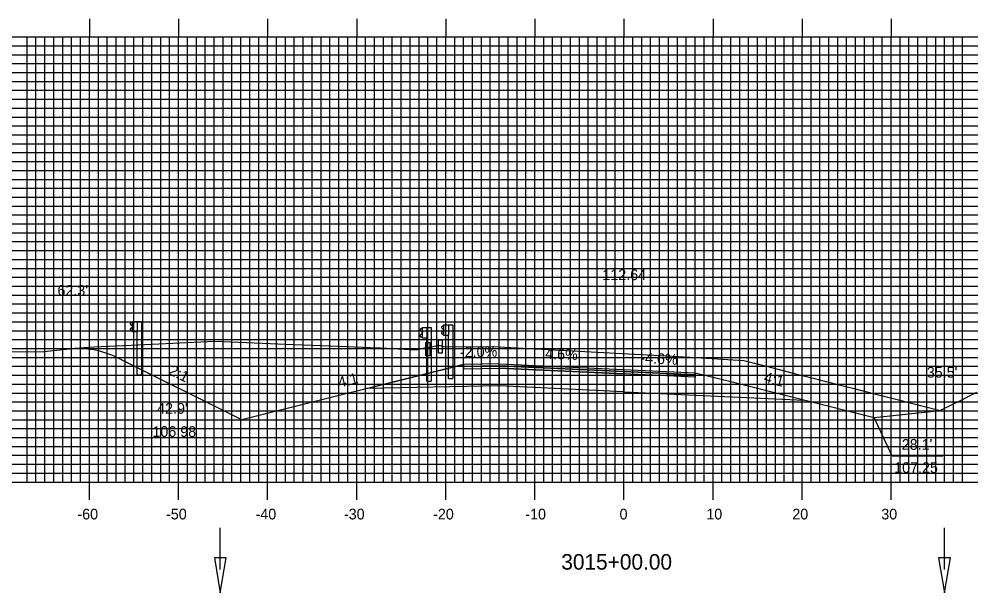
# Model space of a CAD drawing. Extents: x 1684799 to 1685142, y 461260 to 461480.
# Drawn here: x 1684896.8 to 1685003.7, y 461325.6 to 461390.1 of the extents above; entities that cross this region are included whole.
import ezdxf

# ---------------------------------------------------------------- set-up
doc = ezdxf.new("R2010")
doc.units = 0
for name, color, linetype in [('ANNOTATION', 7, 'Continuous'), ('D_Drainage_Ditch_Line', 7, 'Continuous'), ('D_Roadway_Centerline_Text', 7, 'Continuous'), ('D_Roadway_Edge_Shoulder', 7, 'Continuous'), ('D_Roadway_Edge_TW', 7, 'Continuous'), ('D_Roadway_Pavement', 7, 'Continuous'), ('D_Roadway_SlopeLines', 7, 'Continuous'), ('D_Roadway_SubGrade', 7, 'Continuous'), ('D_Text_Standard', 7, 'Continuous'), ('H_V ANNOTATION', 7, 'Continuous'), ('MAJOR', 7, 'Continuous'), ('MINOR', 7, 'Continuous'), ('PDRAIN', 7, 'Continuous'), ('S_Curb_Type_1', 7, 'Continuous'), ('S_Guardrail_Beam', 7, 'Continuous'), ('S_Roadway_Centerline', 7, 'Continuous')]:
    doc.layers.add(name, color=color, linetype=linetype)

msp = doc.modelspace()

# ---------------------------------------------------------------- linework, layer by layer
at = {"layer": 'ANNOTATION'}
msp.add_line((1684978.18, 461351.71), (1684978.94, 461351.52), dxfattribs=at)
msp.add_lwpolyline([(1685000.53, 461340.97), (1684994.84, 461340.97), (1684992.82, 461345.32)], dxfattribs=at)
at = {"layer": 'D_Drainage_Ditch_Line'}
for p, q in [((1684919.41, 461328.23), (1684919.41, 461332.93)), ((1685000.71, 461328.23), (1685000.71, 461332.93))]:
    msp.add_line(p, q, dxfattribs=at)
for points in [[(1684920.06, 461329.55), (1684918.75, 461329.55), (1684919.41, 461325.61)], [(1685001.37, 461329.55), (1685000.05, 461329.55), (1685000.71, 461325.61)]]:
    msp.add_lwpolyline(points, close=True, dxfattribs=at)
at = {"layer": 'D_Roadway_Edge_Shoulder'}
for points in [[(1684950.72, 461351.36), (1684946.72, 461351.28), (1684946.72, 461351.03), (1684950.72, 461351.11)], [(1684950.72, 461351.11), (1684946.72, 461351.03), (1684946.72, 461350.78), (1684950.72, 461350.86)], [(1684964.72, 461350.72), (1684972.72, 461350.35), (1684972.72, 461350.1), (1684964.72, 461350.47)], [(1684964.72, 461350.47), (1684972.72, 461350.1), (1684972.72, 461349.85), (1684964.72, 461350.22)]]:
    msp.add_lwpolyline(points, close=True, dxfattribs=at)
at = {"layer": 'D_Roadway_Edge_TW'}
msp.add_lwpolyline([(1684950.72, 461351.36), (1684964.72, 461350.72), (1684964.72, 461350.47), (1684950.72, 461351.11)], close=True, dxfattribs=at)
at = {"layer": 'D_Roadway_Pavement'}
msp.add_lwpolyline([(1684950.72, 461351.11), (1684964.72, 461350.47), (1684964.72, 461350.22), (1684950.72, 461350.86)], close=True, dxfattribs=at)
for points in [[(1684950.72, 461351.11), (1684950.72, 461350.86)], [(1684950.72, 461351.11), (1684950.72, 461350.86)], [(1684964.72, 461350.47), (1684964.72, 461350.22)], [(1684964.72, 461350.47), (1684964.72, 461350.22)], [(1684964.72, 461350.47), (1684964.72, 461350.22)]]:
    msp.add_lwpolyline(points, dxfattribs=at)
at = {"layer": 'D_Roadway_SlopeLines'}
for p, q in [((1684964.72, 461348.22), (1684984.97, 461347.28)), ((1684992.82, 461345.32), (1685000.22, 461346.1))]:
    msp.add_line(p, q, dxfattribs=at)
for points in [[(1684921.81, 461345.05), (1684907.88, 461352.01)], [(1684946.72, 461351.28), (1684921.81, 461345.05)], [(1684972.72, 461350.35), (1684976.72, 461349.35), (1684992.82, 461345.32)]]:
    msp.add_lwpolyline(points, dxfattribs=at)
msp.add_arc((1684903.41, 461343.07), 10, 63.4349, 95.9937, dxfattribs=at)
at = {"layer": 'D_Roadway_SubGrade'}
for points in [[(1684950.72, 461348.86), (1684935.85, 461348.56), (1684946.72, 461351.28), (1684946.72, 461351.03), (1684950.72, 461351.11), (1684950.72, 461350.86)], [(1684950.72, 461350.86), (1684964.72, 461350.22), (1684964.72, 461348.22), (1684950.72, 461348.86)]]:
    msp.add_lwpolyline(points, close=True, dxfattribs=at)
at = {"layer": 'MAJOR'}
for p, q in [((1684904.72, 461390.08), (1684904.72, 461388.07)), ((1684914.72, 461390.08), (1684914.72, 461388.07)), ((1684924.72, 461390.08), (1684924.72, 461388.07)), ((1684934.72, 461390.08), (1684934.72, 461388.07)), ((1684944.72, 461390.08), (1684944.72, 461388.07)), ((1684954.72, 461390.08), (1684954.72, 461388.07)), ((1684964.72, 461390.08), (1684964.72, 461388.07)), ((1684974.72, 461390.08), (1684974.72, 461388.07)), ((1684984.72, 461390.08), (1684984.72, 461388.07)), ((1684994.72, 461390.08), (1684994.72, 461388.07)), ((1684824.72, 461388.07), (1685104.72, 461388.07)), ((1684824.72, 461388.07), (1685104.72, 461388.07)), ((1684904.72, 461338.07), (1684904.72, 461388.07)), ((1684914.72, 461338.07), (1684914.72, 461388.07)), ((1684924.72, 461338.07), (1684924.72, 461388.07)), ((1684934.72, 461338.07), (1684934.72, 461388.07)), ((1684944.72, 461338.07), (1684944.72, 461388.07)), ((1684954.72, 461338.07), (1684954.72, 461388.07)), ((1684964.72, 461338.07), (1684964.72, 461388.07)), ((1684974.72, 461338.07), (1684974.72, 461388.07)), ((1684984.72, 461338.07), (1684984.72, 461388.07)), ((1684994.72, 461338.07), (1684994.72, 461388.07)), ((1684824.72, 461383.07), (1685104.72, 461383.07)), ((1684824.72, 461378.07), (1685104.72, 461378.07)), ((1684824.72, 461373.07), (1685104.72, 461373.07)), ((1684824.72, 461368.07), (1685104.72, 461368.07)), ((1684824.72, 461363.07), (1685104.72, 461363.07)), ((1684824.72, 461358.07), (1685104.72, 461358.07)), ((1684824.72, 461353.07), (1685104.72, 461353.07)), ((1684824.72, 461348.07), (1685104.72, 461348.07)), ((1684824.72, 461343.07), (1685104.72, 461343.07)), ((1684824.72, 461338.07), (1685104.72, 461338.07)), ((1684824.72, 461338.07), (1685104.72, 461338.07)), ((1684904.72, 461336.07), (1684904.72, 461338.07)), ((1684914.72, 461336.07), (1684914.72, 461338.07)), ((1684924.72, 461336.07), (1684924.72, 461338.07)), ((1684934.72, 461336.07), (1684934.72, 461338.07)), ((1684944.72, 461336.07), (1684944.72, 461338.07)), ((1684954.72, 461336.07), (1684954.72, 461338.07)), ((1684964.72, 461336.07), (1684964.72, 461338.07)), ((1684974.72, 461336.07), (1684974.72, 461338.07)), ((1684984.72, 461336.07), (1684984.72, 461338.07)), ((1684994.72, 461336.07), (1684994.72, 461338.07))]:
    msp.add_line(p, q, dxfattribs=at)
at = {"layer": 'MINOR'}
for p, q in [((1684897.72, 461338.07), (1684897.72, 461388.07)), ((1684898.72, 461338.07), (1684898.72, 461388.07)), ((1684899.72, 461338.07), (1684899.72, 461388.07)), ((1684900.72, 461338.07), (1684900.72, 461388.07)), ((1684901.72, 461338.07), (1684901.72, 461388.07)), ((1684902.72, 461338.07), (1684902.72, 461388.07)), ((1684903.72, 461338.07), (1684903.72, 461388.07)), ((1684905.72, 461338.07), (1684905.72, 461388.07)), ((1684906.72, 461338.07), (1684906.72, 461388.07)), ((1684907.72, 461338.07), (1684907.72, 461388.07)), ((1684908.72, 461338.07), (1684908.72, 461388.07)), ((1684909.72, 461338.07), (1684909.72, 461388.07)), ((1684910.72, 461338.07), (1684910.72, 461388.07)), ((1684911.72, 461338.07), (1684911.72, 461388.07)), ((1684912.72, 461338.07), (1684912.72, 461388.07)), ((1684913.72, 461338.07), (1684913.72, 461388.07)), ((1684915.72, 461338.07), (1684915.72, 461388.07)), ((1684916.72, 461338.07), (1684916.72, 461388.07)), ((1684917.72, 461338.07), (1684917.72, 461388.07)), ((1684918.72, 461338.07), (1684918.72, 461388.07)), ((1684919.72, 461338.07), (1684919.72, 461388.07)), ((1684920.72, 461338.07), (1684920.72, 461388.07)), ((1684921.72, 461338.07), (1684921.72, 461388.07)), ((1684922.72, 461338.07), (1684922.72, 461388.07)), ((1684923.72, 461338.07), (1684923.72, 461388.07)), ((1684925.72, 461338.07), (1684925.72, 461388.07)), ((1684926.72, 461338.07), (1684926.72, 461388.07)), ((1684927.72, 461338.07), (1684927.72, 461388.07)), ((1684928.72, 461338.07), (1684928.72, 461388.07)), ((1684929.72, 461338.07), (1684929.72, 461388.07)), ((1684930.72, 461338.07), (1684930.72, 461388.07)), ((1684931.72, 461338.07), (1684931.72, 461388.07)), ((1684932.72, 461338.07), (1684932.72, 461388.07)), ((1684933.72, 461338.07), (1684933.72, 461388.07)), ((1684935.72, 461338.07), (1684935.72, 461388.07)), ((1684936.72, 461338.07), (1684936.72, 461388.07)), ((1684937.72, 461338.07), (1684937.72, 461388.07)), ((1684938.72, 461338.07), (1684938.72, 461388.07)), ((1684939.72, 461338.07), (1684939.72, 461388.07)), ((1684940.72, 461338.07), (1684940.72, 461388.07)), ((1684941.72, 461338.07), (1684941.72, 461388.07)), ((1684942.72, 461338.07), (1684942.72, 461388.07)), ((1684943.72, 461338.07), (1684943.72, 461388.07)), ((1684945.72, 461338.07), (1684945.72, 461388.07)), ((1684946.72, 461338.07), (1684946.72, 461388.07)), ((1684947.72, 461338.07), (1684947.72, 461388.07)), ((1684948.72, 461338.07), (1684948.72, 461388.07)), ((1684949.72, 461338.07), (1684949.72, 461388.07)), ((1684950.72, 461338.07), (1684950.72, 461388.07)), ((1684951.72, 461338.07), (1684951.72, 461388.07)), ((1684952.72, 461338.07), (1684952.72, 461388.07)), ((1684953.72, 461338.07), (1684953.72, 461388.07)), ((1684955.72, 461338.07), (1684955.72, 461388.07)), ((1684956.72, 461338.07), (1684956.72, 461388.07)), ((1684957.72, 461338.07), (1684957.72, 461388.07)), ((1684958.72, 461338.07), (1684958.72, 461388.07)), ((1684959.72, 461338.07), (1684959.72, 461388.07)), ((1684960.72, 461338.07), (1684960.72, 461388.07)), ((1684961.72, 461338.07), (1684961.72, 461388.07)), ((1684962.72, 461338.07), (1684962.72, 461388.07)), ((1684963.72, 461338.07), (1684963.72, 461388.07)), ((1684965.72, 461338.07), (1684965.72, 461388.07)), ((1684966.72, 461338.07), (1684966.72, 461388.07)), ((1684967.72, 461338.07), (1684967.72, 461388.07)), ((1684968.72, 461338.07), (1684968.72, 461388.07)), ((1684969.72, 461338.07), (1684969.72, 461388.07)), ((1684970.72, 461338.07), (1684970.72, 461388.07)), ((1684971.72, 461338.07), (1684971.72, 461388.07)), ((1684972.72, 461338.07), (1684972.72, 461388.07)), ((1684973.72, 461338.07), (1684973.72, 461388.07)), ((1684975.72, 461338.07), (1684975.72, 461388.07)), ((1684976.72, 461338.07), (1684976.72, 461388.07)), ((1684977.72, 461338.07), (1684977.72, 461388.07)), ((1684978.72, 461338.07), (1684978.72, 461388.07)), ((1684979.72, 461338.07), (1684979.72, 461388.07)), ((1684980.72, 461338.07), (1684980.72, 461388.07)), ((1684981.72, 461338.07), (1684981.72, 461388.07)), ((1684982.72, 461338.07), (1684982.72, 461388.07)), ((1684983.72, 461338.07), (1684983.72, 461388.07)), ((1684985.72, 461338.07), (1684985.72, 461388.07)), ((1684986.72, 461338.07), (1684986.72, 461388.07)), ((1684987.72, 461338.07), (1684987.72, 461388.07)), ((1684988.72, 461338.07), (1684988.72, 461388.07)), ((1684989.72, 461338.07), (1684989.72, 461388.07)), ((1684990.72, 461338.07), (1684990.72, 461388.07)), ((1684991.72, 461338.07), (1684991.72, 461388.07)), ((1684992.72, 461338.07), (1684992.72, 461388.07)), ((1684993.72, 461338.07), (1684993.72, 461388.07)), ((1684995.72, 461338.07), (1684995.72, 461388.07)), ((1684996.72, 461338.07), (1684996.72, 461388.07)), ((1684997.72, 461338.07), (1684997.72, 461388.07)), ((1684998.72, 461338.07), (1684998.72, 461388.07)), ((1684999.72, 461338.07), (1684999.72, 461388.07)), ((1685000.72, 461338.07), (1685000.72, 461388.07)), ((1685001.72, 461338.07), (1685001.72, 461388.07)), ((1685002.72, 461338.07), (1685002.72, 461388.07)), ((1684824.72, 461387.07), (1685104.72, 461387.07)), ((1684824.72, 461386.07), (1685104.72, 461386.07)), ((1684824.72, 461385.07), (1685104.72, 461385.07)), ((1684824.72, 461384.07), (1685104.72, 461384.07)), ((1684824.72, 461382.07), (1685104.72, 461382.07)), ((1684824.72, 461381.07), (1685104.72, 461381.07)), ((1684824.72, 461380.07), (1685104.72, 461380.07)), ((1684824.72, 461379.07), (1685104.72, 461379.07)), ((1684824.72, 461377.07), (1685104.72, 461377.07)), ((1684824.72, 461376.07), (1685104.72, 461376.07)), ((1684824.72, 461375.07), (1685104.72, 461375.07)), ((1684824.72, 461374.07), (1685104.72, 461374.07)), ((1684824.72, 461372.07), (1685104.72, 461372.07)), ((1684824.72, 461371.07), (1685104.72, 461371.07)), ((1684824.72, 461370.07), (1685104.72, 461370.07)), ((1684824.72, 461369.07), (1685104.72, 461369.07)), ((1684824.72, 461367.07), (1685104.72, 461367.07)), ((1684824.72, 461366.07), (1685104.72, 461366.07)), ((1684824.72, 461365.07), (1685104.72, 461365.07)), ((1684824.72, 461364.07), (1685104.72, 461364.07)), ((1684824.72, 461362.07), (1685104.72, 461362.07)), ((1684824.72, 461361.07), (1685104.72, 461361.07)), ((1684824.72, 461360.07), (1685104.72, 461360.07)), ((1684824.72, 461359.07), (1685104.72, 461359.07)), ((1684824.72, 461357.07), (1685104.72, 461357.07)), ((1684824.72, 461356.07), (1685104.72, 461356.07)), ((1684824.72, 461355.07), (1685104.72, 461355.07)), ((1684824.72, 461354.07), (1685104.72, 461354.07)), ((1684824.72, 461352.07), (1685104.72, 461352.07)), ((1684824.72, 461351.07), (1685104.72, 461351.07)), ((1684824.72, 461350.07), (1685104.72, 461350.07)), ((1684824.72, 461349.07), (1685104.72, 461349.07)), ((1684824.72, 461347.07), (1685104.72, 461347.07)), ((1684824.72, 461346.07), (1685104.72, 461346.07)), ((1684824.72, 461345.07), (1685104.72, 461345.07)), ((1684824.72, 461344.07), (1685104.72, 461344.07)), ((1684824.72, 461342.07), (1685104.72, 461342.07)), ((1684824.72, 461341.07), (1685104.72, 461341.07)), ((1684824.72, 461340.07), (1685104.72, 461340.07)), ((1684824.72, 461339.07), (1685104.72, 461339.07))]:
    msp.add_line(p, q, dxfattribs=at)
at = {"layer": 'PDRAIN'}
msp.add_line((1684911.08, 461345.05), (1684921.81, 461345.05), dxfattribs=at)
at = {"layer": 'S_Curb_Type_1'}
for points in [[(1684942.5, 461353.76), (1684942.92, 461353.76), (1684942.92, 461352.26), (1684942.5, 461352.26)], [(1684942.5, 461353.76), (1684942.92, 461353.76), (1684942.92, 461352.26), (1684942.5, 461352.26)], [(1684943.89, 461354.03), (1684944.3, 461354.03), (1684944.3, 461352.53), (1684943.89, 461352.53)], [(1684943.89, 461354.03), (1684944.3, 461354.03), (1684944.3, 461352.53), (1684943.89, 461352.53)]]:
    msp.add_lwpolyline(points, close=True, dxfattribs=at)
at = {"layer": 'S_Guardrail_Beam'}
for p, q in [((1684909.47, 461356.02), (1684909.33, 461355.92)), ((1684909.47, 461356.02), (1684909.33, 461355.92)), ((1684909.33, 461355.78), (1684909.52, 461355.65)), ((1684909.33, 461355.78), (1684909.52, 461355.65)), ((1684909.57, 461356.05), (1684909.49, 461356.03)), ((1684909.57, 461356.05), (1684909.49, 461356.03)), ((1684909.56, 461355.58), (1684909.56, 461355.49)), ((1684909.56, 461355.58), (1684909.56, 461355.49)), ((1684909.57, 461356.12), (1684910.06, 461356.12)), ((1684909.57, 461354.95), (1684909.57, 461356.12)), ((1684909.57, 461356.12), (1684910.06, 461356.12)), ((1684909.57, 461354.95), (1684909.57, 461356.12)), ((1684910.06, 461356.12), (1684910.55, 461356.12)), ((1684910.06, 461356.12), (1684910.06, 461354.95)), ((1684910.06, 461356.12), (1684910.55, 461356.12)), ((1684910.06, 461356.12), (1684910.06, 461354.95)), ((1684910.55, 461356.12), (1684910.55, 461350.12)), ((1684910.55, 461356.12), (1684910.55, 461350.12)), ((1684944.42, 461355.62), (1684944.27, 461355.52)), ((1684944.42, 461355.62), (1684944.27, 461355.52)), ((1684944.52, 461355.64), (1684944.43, 461355.62)), ((1684944.52, 461355.64), (1684944.43, 461355.62)), ((1684944.52, 461355.71), (1684945.01, 461355.71)), ((1684944.52, 461354.54), (1684944.52, 461355.71)), ((1684944.52, 461355.71), (1684945.01, 461355.71)), ((1684944.52, 461354.54), (1684944.52, 461355.71)), ((1684945.01, 461355.71), (1684945.5, 461355.71)), ((1684945.01, 461355.71), (1684945.01, 461354.54)), ((1684945.01, 461355.71), (1684945.5, 461355.71)), ((1684945.01, 461355.71), (1684945.01, 461354.54)), ((1684945.5, 461355.71), (1684945.5, 461349.71)), ((1684945.5, 461355.71), (1684945.5, 461349.71)), ((1684909.52, 461355.43), (1684909.33, 461355.29)), ((1684909.52, 461355.43), (1684909.33, 461355.29)), ((1684909.33, 461355.15), (1684909.47, 461355.05)), ((1684909.33, 461355.15), (1684909.47, 461355.05)), ((1684909.49, 461355.04), (1684909.57, 461355.03)), ((1684909.49, 461355.04), (1684909.57, 461355.03)), ((1684910.06, 461354.95), (1684909.57, 461354.95)), ((1684910.06, 461354.95), (1684909.57, 461354.95)), ((1684910.06, 461350.12), (1684910.06, 461354.95)), ((1684910.06, 461350.12), (1684910.06, 461354.95)), ((1684942.01, 461355.32), (1684941.86, 461355.22)), ((1684942.01, 461355.32), (1684941.86, 461355.22)), ((1684941.86, 461355.07), (1684942.06, 461354.94)), ((1684941.86, 461355.07), (1684942.06, 461354.94)), ((1684942.06, 461354.72), (1684941.86, 461354.58)), ((1684942.06, 461354.72), (1684941.86, 461354.58)), ((1684942.1, 461355.34), (1684942.02, 461355.32)), ((1684942.1, 461355.34), (1684942.02, 461355.32)), ((1684942.09, 461354.87), (1684942.09, 461354.78)), ((1684942.09, 461354.87), (1684942.09, 461354.78)), ((1684942.1, 461355.41), (1684942.59, 461355.41)), ((1684942.1, 461354.24), (1684942.1, 461355.41)), ((1684942.1, 461355.41), (1684942.59, 461355.41)), ((1684942.1, 461354.24), (1684942.1, 461355.41)), ((1684942.59, 461355.41), (1684943.09, 461355.41)), ((1684942.59, 461355.41), (1684942.59, 461354.24)), ((1684942.59, 461355.41), (1684943.09, 461355.41)), ((1684942.59, 461355.41), (1684942.59, 461354.24)), ((1684943.09, 461355.41), (1684943.09, 461349.41)), ((1684943.09, 461355.41), (1684943.09, 461349.41)), ((1684944.27, 461355.37), (1684944.47, 461355.24)), ((1684944.27, 461355.37), (1684944.47, 461355.24)), ((1684944.47, 461355.02), (1684944.27, 461354.88)), ((1684944.47, 461355.02), (1684944.27, 461354.88)), ((1684944.27, 461354.74), (1684944.42, 461354.64)), ((1684944.27, 461354.74), (1684944.42, 461354.64)), ((1684944.43, 461354.63), (1684944.52, 461354.62)), ((1684944.43, 461354.63), (1684944.52, 461354.62)), ((1684944.5, 461355.17), (1684944.5, 461355.08)), ((1684944.5, 461355.17), (1684944.5, 461355.08)), ((1684945.01, 461354.54), (1684944.52, 461354.54)), ((1684945.01, 461354.54), (1684944.52, 461354.54)), ((1684945.01, 461349.71), (1684945.01, 461354.54)), ((1684945.01, 461349.71), (1684945.01, 461354.54)), ((1684941.86, 461354.44), (1684942.01, 461354.34)), ((1684941.86, 461354.44), (1684942.01, 461354.34)), ((1684942.02, 461354.33), (1684942.1, 461354.32)), ((1684942.02, 461354.33), (1684942.1, 461354.32)), ((1684942.59, 461354.24), (1684942.1, 461354.24)), ((1684942.59, 461354.24), (1684942.1, 461354.24)), ((1684942.59, 461349.41), (1684942.59, 461354.24)), ((1684942.59, 461349.41), (1684942.59, 461354.24)), ((1684910.06, 461350.12), (1684910.55, 461350.12)), ((1684910.06, 461350.12), (1684910.55, 461350.12)), ((1684942.59, 461349.41), (1684943.09, 461349.41)), ((1684942.59, 461349.41), (1684943.09, 461349.41)), ((1684945.01, 461349.71), (1684945.5, 461349.71)), ((1684945.01, 461349.71), (1684945.5, 461349.71))]:
    msp.add_line(p, q, dxfattribs=at)
for centre, major_axis, start_param, end_param in [((1684909.38, 461355.85), (-0.0877, 0), 5.323254, 7.243116), ((1684909.38, 461355.85), (-0.0877, 0), 5.323254, 7.243116), ((1684909.5, 461355.99), (-0.0417, 0), 4.886922, 5.323254), ((1684909.5, 461355.99), (-0.0417, 0), 4.886922, 5.323254), ((1684909.48, 461355.58), (0.0789, 0), 0, 0.959931), ((1684909.48, 461355.58), (0.0789, 0), 0, 0.959931), ((1684944.44, 461355.58), (-0.0417, 0), 4.886922, 5.323254), ((1684944.44, 461355.58), (-0.0417, 0), 4.886922, 5.323254), ((1684909.38, 461355.22), (-0.0877, 0), 5.323254, 7.243116), ((1684909.38, 461355.22), (-0.0877, 0), 5.323254, 7.243116), ((1684909.5, 461355.08), (-0.0417, 0), 0.959931, 1.396263), ((1684909.5, 461355.08), (-0.0417, 0), 0.959931, 1.396263), ((1684909.48, 461355.49), (0.0789, 0), 5.323254, 6.283185), ((1684909.48, 461355.49), (0.0789, 0), 5.323254, 6.283185), ((1684941.91, 461355.14), (-0.0877, 0), 5.323254, 7.243116), ((1684941.91, 461355.14), (-0.0877, 0), 5.323254, 7.243116), ((1684941.91, 461354.51), (-0.0877, 0), 5.323254, 7.243116), ((1684941.91, 461354.51), (-0.0877, 0), 5.323254, 7.243116), ((1684942.03, 461355.28), (-0.0417, 0), 4.886922, 5.323254), ((1684942.03, 461355.28), (-0.0417, 0), 4.886922, 5.323254), ((1684942.01, 461354.87), (0.0789, 0), 0, 0.959931), ((1684942.01, 461354.87), (0.0789, 0), 0, 0.959931), ((1684942.01, 461354.78), (0.0789, 0), 5.323254, 6.283185), ((1684942.01, 461354.78), (0.0789, 0), 5.323254, 6.283185), ((1684944.32, 461355.45), (-0.0877, 0), 5.323254, 7.243116), ((1684944.32, 461355.45), (-0.0877, 0), 5.323254, 7.243116), ((1684944.32, 461354.81), (-0.0877, 0), 5.323254, 7.243116), ((1684944.32, 461354.81), (-0.0877, 0), 5.323254, 7.243116), ((1684944.44, 461354.67), (-0.0417, 0), 0.959931, 1.396263), ((1684944.44, 461354.67), (-0.0417, 0), 0.959931, 1.396263), ((1684944.42, 461355.17), (0.0789, 0), 0, 0.959931), ((1684944.42, 461355.17), (0.0789, 0), 0, 0.959931), ((1684944.42, 461355.08), (0.0789, 0), 5.323254, 6.283185), ((1684944.42, 461355.08), (0.0789, 0), 5.323254, 6.283185), ((1684942.03, 461354.37), (-0.0417, 0), 0.959931, 1.396263), ((1684942.03, 461354.37), (-0.0417, 0), 0.959931, 1.396263)]:
    msp.add_ellipse(centre, major_axis=major_axis, ratio=0.995501, start_param=start_param, end_param=end_param, dxfattribs=at)
at = {"layer": 'S_Roadway_Centerline'}
for points in [[(1684895.77, 461352.69), (1684899.59, 461352.72), (1684903.62, 461353.15), (1684905.2, 461353.26), (1684909.35, 461353.44), (1684918.78, 461353.89), (1684926.75, 461353.57), (1684931.61, 461353.37), (1684933.61, 461353.29), (1684936.22, 461353.2), (1684937.4, 461353.15), (1684941.39, 461352.93), (1684941.69, 461352.98), (1684942.5, 461353.18), (1684942.95, 461353.23), (1684943.89, 461353.44), (1684944.07, 461353.4), (1684944.48, 461353.29), (1684947.15, 461353.27), (1684949.97, 461353.28), (1684963.1, 461352.58), (1684969.51, 461352.24), (1684973.44, 461352.01), (1684978.18, 461351.71)], [(1684978.94, 461351.52), (1684980.72, 461351.07), (1684984.28, 461350.16), (1684985.81, 461349.77), (1684989.62, 461348.81), (1684990.57, 461348.57), (1684992.69, 461348.03), (1684994.94, 461347.45), (1684995.39, 461347.34), (1685000.22, 461346.1), (1685001.66, 461346.82), (1685002.19, 461347.08), (1685004.33, 461348.15)]]:
    msp.add_lwpolyline(points, dxfattribs=at)

# ---------------------------------------------------------------- texts
at = {"layer": 'ANNOTATION'}
for s, rotation, p in [('-2.0%', 1.1458, (1684946.32, 461352.07)), ('4.6%', 357.3663, (1684955.86, 461351.92)), ('-4.6%', 357.3663, (1684966.54, 461351.43)), ('2:1', 333.4349, (1684913.52, 461350.23)), ('4:1', 14.0362, (1684932.8, 461348.66)), ('4:1', 345.9638, (1684980.35, 461349.3))]:
    msp.add_text(s, height=1.2, rotation=rotation, dxfattribs=at).set_placement(p)
for s, p in [("42.9' ", (1684912.32, 461345.74)), ('106.98', (1684911.79, 461343.14)), ("28.1' ", (1684995.91, 461341.69)), ('107.25', (1684995.06, 461339.09))]:
    msp.add_text(s, height=1.2, dxfattribs=at).set_placement(p)
at = {"layer": 'D_Roadway_Centerline_Text'}
msp.add_text('112.64', height=1.2, dxfattribs=at).set_placement((1684962.3, 461360.75))
at = {"layer": 'D_Text_Standard'}
for s, p in [("62.3'", (1684901.13, 461359)), ("35.5'", (1684998.72, 461349.8))]:
    msp.add_text(s, height=1.2, dxfattribs=at).set_placement(p)
at = {"layer": 'H_V ANNOTATION'}
for s, height, p in [('-60', 1.2, (1684903.37, 461333.87)), ('-50', 1.2, (1684913.32, 461333.87)), ('-40', 1.2, (1684923.37, 461333.87)), ('-30', 1.2, (1684933.29, 461333.87)), ('-20', 1.2, (1684943.3, 461333.87)), ('-10', 1.2, (1684953.65, 461333.87)), ('0', 1.2, (1684964.23, 461333.87)), ('10', 1.2, (1684973.97, 461333.87)), ('20', 1.2, (1684983.62, 461333.87)), ('30', 1.2, (1684993.61, 461333.87)), ('3015+00.00', 1.75, (1684957.69, 461328.23))]:
    msp.add_text(s, height=height, dxfattribs=at).set_placement(p)

doc.saveas('drawing.dxf')
